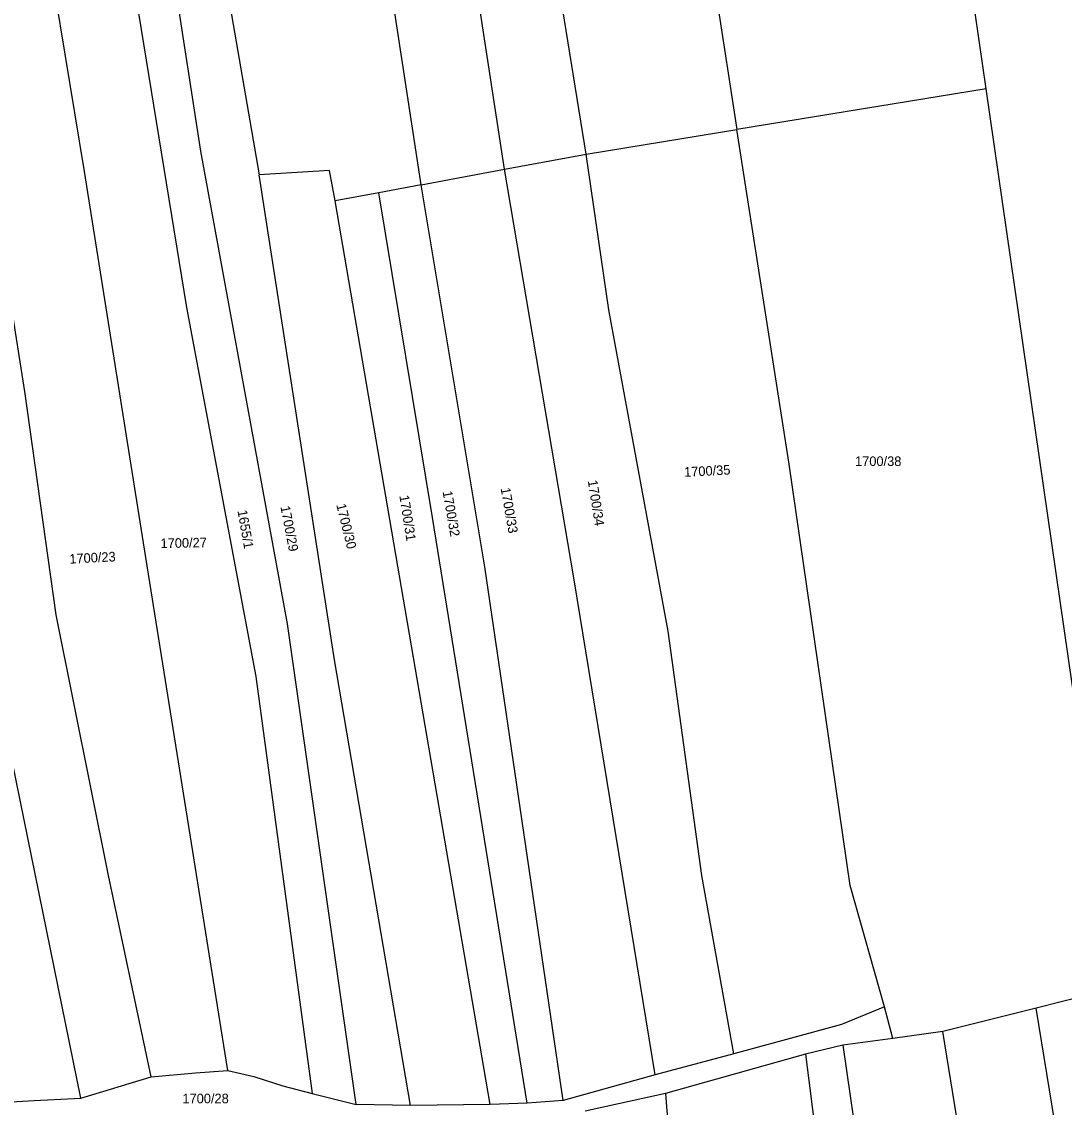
# Model space of a CAD drawing. Extents: x -776734 to -748832, y -1118122 to -976986.
# Drawn here: x -752933.8 to -752749.1, y -1116019.1 to -1115826.7 of the extents above; entities that cross this region are included whole.
import ezdxf

# ---------------------------------------------------------------- set-up
doc = ezdxf.new("R2010")
doc.units = 0
doc.layers.add('KM_Hranice parcel', color=7, linetype='Continuous')
doc.layers.add('KM_Parcelní čísla', color=7, linetype='Continuous')

msp = doc.modelspace()

# ---------------------------------------------------------------- linework, layer by layer
at = {"layer": 'KM_Hranice parcel'}
for p, q in [((-752848.25, -1115852.83), (-752858.96, -1115783.05)), ((-752833.78, -1115850.14), (-752844.67, -1115782.9)), ((-752863.02, -1115855.58), (-752873.85, -1115785.05)), ((-752816.22, -1115786.21), (-752807.07, -1115845.79)), ((-752902.84, -1115789.42), (-752891.74, -1115853.8)), ((-752762.91, -1115838.6), (-752807.07, -1115845.79)), ((-752744.62, -1115965.33), (-752762.91, -1115838.6)), ((-752833.78, -1115850.14), (-752807.07, -1115845.79)), ((-752848.25, -1115852.83), (-752833.78, -1115850.14)), ((-752863.02, -1115855.58), (-752848.25, -1115852.83)), ((-752863.02, -1115855.58), (-752870.55, -1115856.98)), ((-752870.55, -1115856.98), (-752878.27, -1115858.42)), ((-752923.32, -1116017.46), (-752938.14, -1115944.88)), ((-752741, -1115998.22), (-752754.05, -1116001.5)), ((-752779.47, -1116006.9), (-752780.92, -1116001.27)), ((-752754.05, -1116001.5), (-752770.59, -1116005.66)), ((-752770.59, -1116005.66), (-752779.47, -1116006.9)), ((-752788.29, -1116008.08), (-752794.92, -1116009.69)), ((-752779.47, -1116006.9), (-752788.29, -1116008.08)), ((-752807.62, -1116009.59), (-752821.56, -1116013.32)), ((-752794.92, -1116009.69), (-752819.73, -1116016.65)), ((-752923.32, -1116017.46), (-752910.9, -1116013.69)), ((-752821.56, -1116013.32), (-752837.85, -1116017.86)), ((-752882.34, -1116016.65), (-752874.56, -1116018.59)), ((-752837.85, -1116017.86), (-752844.24, -1116018.36)), ((-752819.73, -1116016.65), (-752833.98, -1116019.74)), ((-752864.92, -1116018.75), (-752874.56, -1116018.59)), ((-752850.82, -1116018.59), (-752864.92, -1116018.75)), ((-752844.24, -1116018.36), (-752850.82, -1116018.59))]:
    msp.add_line(p, q, dxfattribs=at)
for points in [[(-752921.98, -1115769), (-752918.47, -1115792.11), (-752904.6, -1115877.3), (-752892.34, -1115942.7), (-752882.34, -1116016.65)], [(-752874.56, -1116018.59), (-752886.74, -1115933.4), (-752902.09, -1115849.61), (-752914.64, -1115768.08)], [(-752762.91, -1115838.6), (-752766.17, -1115816.08), (-752768.64, -1115801.76), (-752771.29, -1115790.38), (-752775.93, -1115776.97)], [(-752897.28, -1116012.56), (-752911.8, -1115921.63), (-752922.68, -1115853.22), (-752932.99, -1115790.77)], [(-752910.9, -1116013.69), (-752918.46, -1115977.99), (-752927.69, -1115931.82), (-752933.29, -1115892.2), (-752942.79, -1115832.06)], [(-752780.92, -1116001.27), (-752787.02, -1115979.8), (-752797.84, -1115905.08), (-752807.07, -1115845.79)], [(-752807.62, -1116009.59), (-752813.3, -1115977.98), (-752819.27, -1115934.7), (-752829.79, -1115877.77), (-752833.78, -1115850.14)], [(-752878.27, -1115858.42), (-752879.27, -1115853.07), (-752891.74, -1115853.8)], [(-752864.92, -1116018.75), (-752878.39, -1115939.76), (-752891.74, -1115853.8)], [(-752821.56, -1116013.32), (-752835.9, -1115925.6), (-752848.25, -1115852.83)], [(-752837.85, -1116017.86), (-752851.76, -1115923.29), (-752863.02, -1115855.58)], [(-752844.24, -1116018.36), (-752861.03, -1115914.56), (-752870.55, -1115856.98)], [(-752850.82, -1116018.59), (-752865.83, -1115931.07), (-752878.27, -1115858.42)], [(-752780.92, -1116001.27), (-752788.57, -1116004.39), (-752795.06, -1116006.19), (-752807.62, -1116009.59)], [(-752709.42, -1116278.87), (-752719.17, -1116216.27), (-752731.88, -1116129.75), (-752745.61, -1116053.27), (-752754.05, -1116001.5)], [(-752727.08, -1116276.53), (-752742.8, -1116178.35), (-752755.07, -1116101.46), (-752770.59, -1116005.66)], [(-752788.29, -1116008.08), (-752781.04, -1116058.28), (-752774.81, -1116086.49), (-752763.64, -1116156.43), (-752752.27, -1116229.8), (-752749.26, -1116245.27), (-752744.78, -1116275.04)], [(-752794.92, -1116009.69), (-752788.84, -1116057.75), (-752781.58, -1116086.05), (-752769.8, -1116158.18), (-752757.71, -1116239.45), (-752752.86, -1116269.38), (-752751.79, -1116275.35)], [(-752910.9, -1116013.69), (-752903, -1116012.98), (-752897.28, -1116012.56)], [(-752897.28, -1116012.56), (-752892.68, -1116013.63), (-752887.53, -1116015.27), (-752882.34, -1116016.65)], [(-752950.51, -1116019.14), (-752947.06, -1116018.92), (-752938.79, -1116018.27), (-752931.58, -1116017.87), (-752923.32, -1116017.46)], [(-752819.73, -1116016.65), (-752816.11, -1116063.04), (-752810.43, -1116086.24), (-752801.58, -1116134.68), (-752793.3, -1116186.59), (-752788.01, -1116237.14), (-752780.22, -1116265.74), (-752776.97, -1116282.01), (-752775.8, -1116292.56)]]:
    msp.add_lwpolyline(points, dxfattribs=at)

# ---------------------------------------------------------------- texts
at = {"layer": 'KM_Parcelní čísla'}
for s, p in [('1700/38', (-752786.15, -1115905.42)), ('1700/28', (-752905.34, -1116018.37))]:
    msp.add_text(s, height=1.7, dxfattribs=at).set_placement(p)
for s, rotation, p in [('1700/35', 3, (-752816.395, -1115907.348)), ('1700/34', 279, (-752833.509, -1115908.032)), ('1700/32', 280, (-752859.247, -1115909.957)), ('1700/33', 280, (-752848.957, -1115909.377)), ('1700/31', 279, (-752866.899, -1115910.702)), ('1655/1', 280, (-752895.587, -1115913.357)), ('1700/29', 281, (-752887.984, -1115912.632)), ('1700/30', 284, (-752878.084, -1115912.305)), ('1700/27', 1, (-752909.205, -1115919.969)), ('1700/23', 3, (-752925.335, -1115922.738))]:
    msp.add_text(s, height=1.7, rotation=rotation, dxfattribs=at).set_placement(p)

doc.saveas('drawing.dxf')
